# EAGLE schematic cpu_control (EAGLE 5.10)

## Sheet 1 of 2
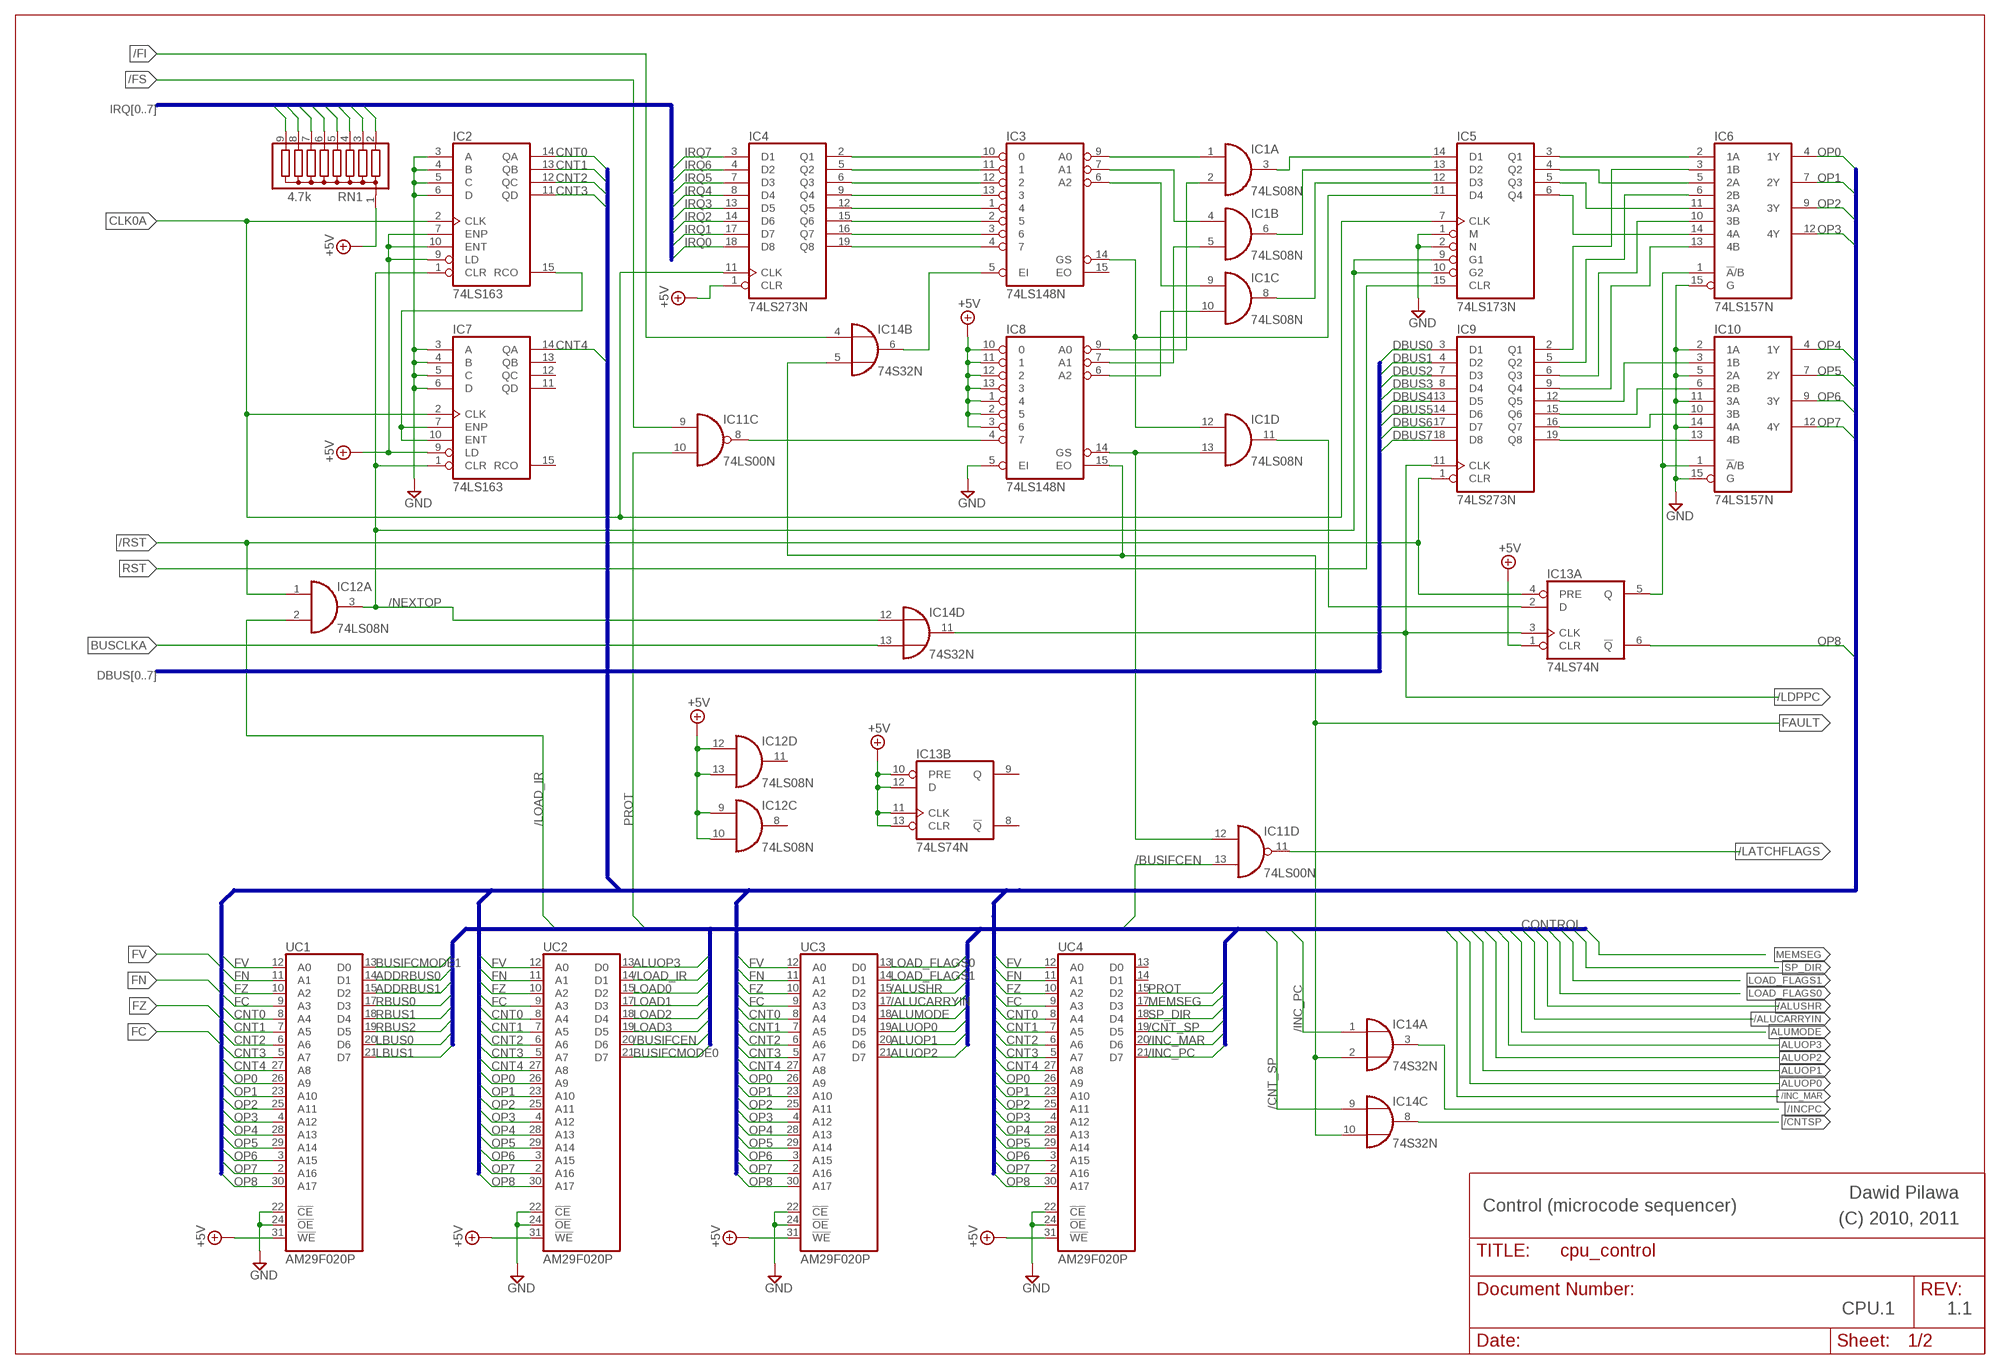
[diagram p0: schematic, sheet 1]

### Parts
IC1  74LS08N  [DIL14]
IC2  74LS163  74160N  [DIL16]
IC3  74LS148N  [DIL16]
IC4  74LS273N  74273N  [DIL20]
IC5  74LS173N  [DIL16]
IC6  74LS157N  [DIL16]
IC7  74LS163  74160N  [DIL16]
IC8  74LS148N  [DIL16]
IC9  74LS273N  74273N  [DIL20]
IC10  74LS157N  [DIL16]
IC11  74LS00N  [DIL14]
IC12  74LS08N  [DIL14]
IC13  74LS74N  [DIL14]
IC14  74S32N  [DIL14]
RN1  4.7k  G08R  [SIL9]
UC1  AM29F020P  [DIL32-6]
UC2  AM29F020P  [DIL32-6]
UC3  AM29F020P  [DIL32-6]
UC4  AM29F020P  [DIL32-6]

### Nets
+5V: IC2.7(ENP) IC2.9(LD) IC2.10(ENT) IC4.1(CLR) IC7.9(LD) IC8.1 IC8.2 IC8.3 IC8.10 IC8.11 IC8.12 IC8.13 IC12.9(C:I0) IC12.10(C:I1) IC12.12(D:I0) IC12.13(D:I1) IC13.1(A:CLR) IC13.10(B:PRE) IC13.11(B:CLK) IC13.12(B:D) IC13.13(B:CLR) RN1.1 UC1.31(!WE) UC2.31(!WE) UC3.31(!WE) UC4.31(!WE) ; also sheet 2
/ALUCARRYIN: UC3.17(D3)
/ALUSHR: UC3.15(D2)
/BUSIFCEN: IC11.13(D:I1) UC2.20(D6) ; also sheet 2
/CNT_SP: IC14.9(C:I0) UC4.19(D5)
/CNTSP: IC14.8(C:O)
/FAULT_PF: IC8.4 IC11.8(C:O)
/FI: IC14.4(B:I0) ; also sheet 2
/FS: IC11.9(C:I0) ; also sheet 2
/INC_MAR: UC4.20(D6)
/INC_PC: IC14.1(A:I0) UC4.21(D7)
/INCPC: IC14.3(A:O)
/LATCHFLAGS: IC11.11(D:O) ; also sheet 2
/LDPPC: IC9.11(CLK) IC13.3(A:CLK) IC14.11(D:O)
/LOAD_IR: IC12.2(A:I1) UC2.14(D1)
/NEXTOP: IC2.1(CLR) IC5.9(G1) IC5.10(G2) IC7.1(CLR) IC12.3(A:O) IC14.12(D:I0)
/RST: IC9.1(CLR) IC12.1(A:I0) IC13.4(A:PRE) ; also sheet 2
ADDRBUS0: UC1.14(D1) ; also sheet 2
ADDRBUS1: UC1.15(D2) ; also sheet 2
ALUMODE: UC3.18(D4)
ALUOP0: UC3.19(D5)
ALUOP1: UC3.20(D6)
ALUOP2: UC3.21(D7)
ALUOP3: UC2.13(D0)
BUSCLKA: IC14.13(D:I1) ; also sheet 2
BUSIFCMODE0: UC2.21(D7) ; also sheet 2
BUSIFCMODE1: UC1.13(D0) ; also sheet 2
CLK0A: IC2.2(CLK) IC4.11(CLK) IC5.7(CLK) IC7.2(CLK)
CNT0: IC2.14(QA) UC1.8(A4) UC2.8(A4) UC3.8(A4) UC4.8(A4)
CNT1: IC2.13(QB) UC1.7(A5) UC2.7(A5) UC3.7(A5) UC4.7(A5)
CNT2: IC2.12(QC) UC1.6(A6) UC2.6(A6) UC3.6(A6) UC4.6(A6)
CNT3: IC2.11(QD) UC1.5(A7) UC2.5(A7) UC3.5(A7) UC4.5(A7)
CNT4: IC7.14(QA) UC1.27(A8) UC2.27(A8) UC3.27(A8) UC4.27(A8)
DBUS0: IC9.3(D1)
DBUS1: IC9.4(D2)
DBUS2: IC9.7(D3)
DBUS3: IC9.8(D4)
DBUS4: IC9.13(D5)
DBUS5: IC9.14(D6)
DBUS6: IC9.17(D7)
DBUS7: IC9.18(D8)
FAULT: IC8.15(EO) IC14.2(A:I1) IC14.5(B:I1) IC14.10(C:I1) ; also sheet 2
FC: UC1.9(A3) UC2.9(A3) UC3.9(A3) UC4.9(A3) ; also sheet 2
FN: UC1.11(A1) UC2.11(A1) UC3.11(A1) UC4.11(A1) ; also sheet 2
FV: UC1.12(A0) UC2.12(A0) UC3.12(A0) UC4.12(A0) ; also sheet 2
FZ: UC1.10(A2) UC2.10(A2) UC3.10(A2) UC4.10(A2) ; also sheet 2
GND: IC2.3(A) IC2.4(B) IC2.5(C) IC2.6(D) IC5.1(M) IC5.2(N) IC6.15(G) IC7.3(A) IC7.4(B) IC7.5(C) IC7.6(D) IC8.5(EI) IC10.2(1A) IC10.5(2A) IC10.11(3A) IC10.14(4A) IC10.15(G) UC1.22(!CE) UC1.24(!OE) UC2.22(!CE) UC2.24(!OE) UC3.22(!CE) UC3.24(!OE) UC4.22(!CE) UC4.24(!OE) ; also sheet 2
IRQ0: IC4.18(D8) RN1.9
IRQ1: IC4.17(D7) RN1.7 RN1.8
IRQ2: IC4.14(D6)
IRQ3: IC4.13(D5) RN1.6
IRQ4: IC4.8(D4) RN1.5
IRQ5: IC4.7(D3) RN1.3 RN1.4
IRQ6: IC4.4(D2)
IRQ7: IC4.3(D1) RN1.2
LBUS0: UC1.20(D6) ; also sheet 2
LBUS1: UC1.21(D7) ; also sheet 2
LOAD0: UC2.15(D2) ; also sheet 2
LOAD1: UC2.17(D3) ; also sheet 2
LOAD2: UC2.18(D4) ; also sheet 2
LOAD3: UC2.19(D5) ; also sheet 2
LOAD_FLAGS0: UC3.13(D0) ; also sheet 2
LOAD_FLAGS1: UC3.14(D1) ; also sheet 2
MEMSEG: UC4.17(D3)
N$1: IC1.1(A:I0) IC3.9(A0)
N$2: IC2.15(RCO) IC7.7(ENP) IC7.10(ENT)
N$3: IC1.2(A:I1) IC8.9(A0)
N$4: IC1.4(B:I0) IC3.7(A1)
N$5: IC1.5(B:I1) IC8.7(A1)
N$6: IC1.10(C:I1) IC8.6(A2)
N$7: IC1.9(C:I0) IC3.6(A2)
N$9: IC1.12(D:I0) IC3.14(GS) IC5.11(D4)
N$10: IC1.13(D:I1) IC8.14(GS) IC11.12(D:I0)
N$11: IC1.3(A:O) IC5.14(D1)
N$12: IC1.6(B:O) IC5.13(D2)
N$13: IC1.8(C:O) IC5.12(D3)
N$14: IC1.11(D:O) IC13.2(A:D)
N$16: IC6.6(2B) IC9.5(Q2)
N$18: IC5.3(Q1) IC6.2(1A)
N$19: IC5.4(Q2) IC6.5(2A)
N$20: IC5.5(Q3) IC6.11(3A)
N$21: IC5.6(Q4) IC6.14(4A)
N$22: IC9.19(Q8) IC10.13(4B)
N$23: IC9.16(Q7) IC10.10(3B)
N$24: IC9.15(Q6) IC10.6(2B)
N$25: IC9.12(Q5) IC10.3(1B)
N$26: IC6.3(1B) IC9.2(Q1)
N$27: IC3.5(EI) IC14.6(B:O)
N$28: IC6.10(3B) IC9.6(Q3)
N$30: IC6.13(4B) IC9.9(Q4)
N$47: IC6.1(!A!/B) IC10.1(!A!/B) IC13.5(A:Q)
N$57: IC3.4 IC4.19(Q8)
N$58: IC3.3 IC4.16(Q7)
N$59: IC3.2 IC4.15(Q6)
N$60: IC3.1 IC4.12(Q5)
N$61: IC3.13 IC4.9(Q4)
N$62: IC3.12 IC4.6(Q3)
N$63: IC3.11 IC4.5(Q2)
N$64: IC3.10 IC4.2(Q1)
OP0: IC6.4(1Y) UC1.26(A9) UC2.26(A9) UC3.26(A9) UC4.26(A9)
OP1: IC6.7(2Y) UC1.23(A10) UC2.23(A10) UC3.23(A10) UC4.23(A10)
OP2: IC6.9(3Y) UC1.25(A11) UC2.25(A11) UC3.25(A11) UC4.25(A11)
OP3: IC6.12(4Y) UC1.4(A12) UC2.4(A12) UC3.4(A12) UC4.4(A12)
OP4: IC10.4(1Y) UC1.28(A13) UC2.28(A13) UC3.28(A13) UC4.28(A13)
OP5: IC10.7(2Y) UC1.29(A14) UC2.29(A14) UC3.29(A14) UC4.29(A14)
OP6: IC10.9(3Y) UC1.3(A15) UC2.3(A15) UC3.3(A15) UC4.3(A15)
OP7: IC10.12(4Y) UC1.2(A16) UC2.2(A16) UC3.2(A16) UC4.2(A16)
OP8: IC13.6(A:!Q) UC1.30(A17) UC2.30(A17) UC3.30(A17) UC4.30(A17)
PROT: IC11.10(C:I1) UC4.15(D2)
RBUS0: UC1.17(D3) ; also sheet 2
RBUS1: UC1.18(D4) ; also sheet 2
RBUS2: UC1.19(D5) ; also sheet 2
RST: IC5.15(CLR) ; also sheet 2
SP_DIR: UC4.18(D4)
Unconnected: IC3.15(EO) IC7.11(QD) IC7.12(QC) IC7.13(QB) IC7.15(RCO) IC12.8(C:O) IC12.11(D:O) IC13.8(B:!Q) IC13.9(B:Q) UC4.13(D0) UC4.14(D1)

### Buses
DBUS[0..7]
UCADR:OP[0..8],CNT[0..4],FC,FZ,FN,FV
IRQ[0..7]
UCODE:LBUS[0..1],RBUS[0..2],ADDRBUS[0..1],BUSIFCMODE[0..1],/BUSIFCEN,LOAD[0..3],/LOAD_IR,ALUOP[0..3],ALUMODE,/ALUCARRYIN,/ALUSHR,LOAD_FLAGS[0..1],/INC_PC,/INC_MAR,/CNT_SP,SP_DIR,MEMSEG,PROT,NC[0..1],NEXTOP

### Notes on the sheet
- CONTROL
- Dawid Pilawa
- Control (microcode sequencer) | (C) 2010, 2011
- CPU.1 | 1.1

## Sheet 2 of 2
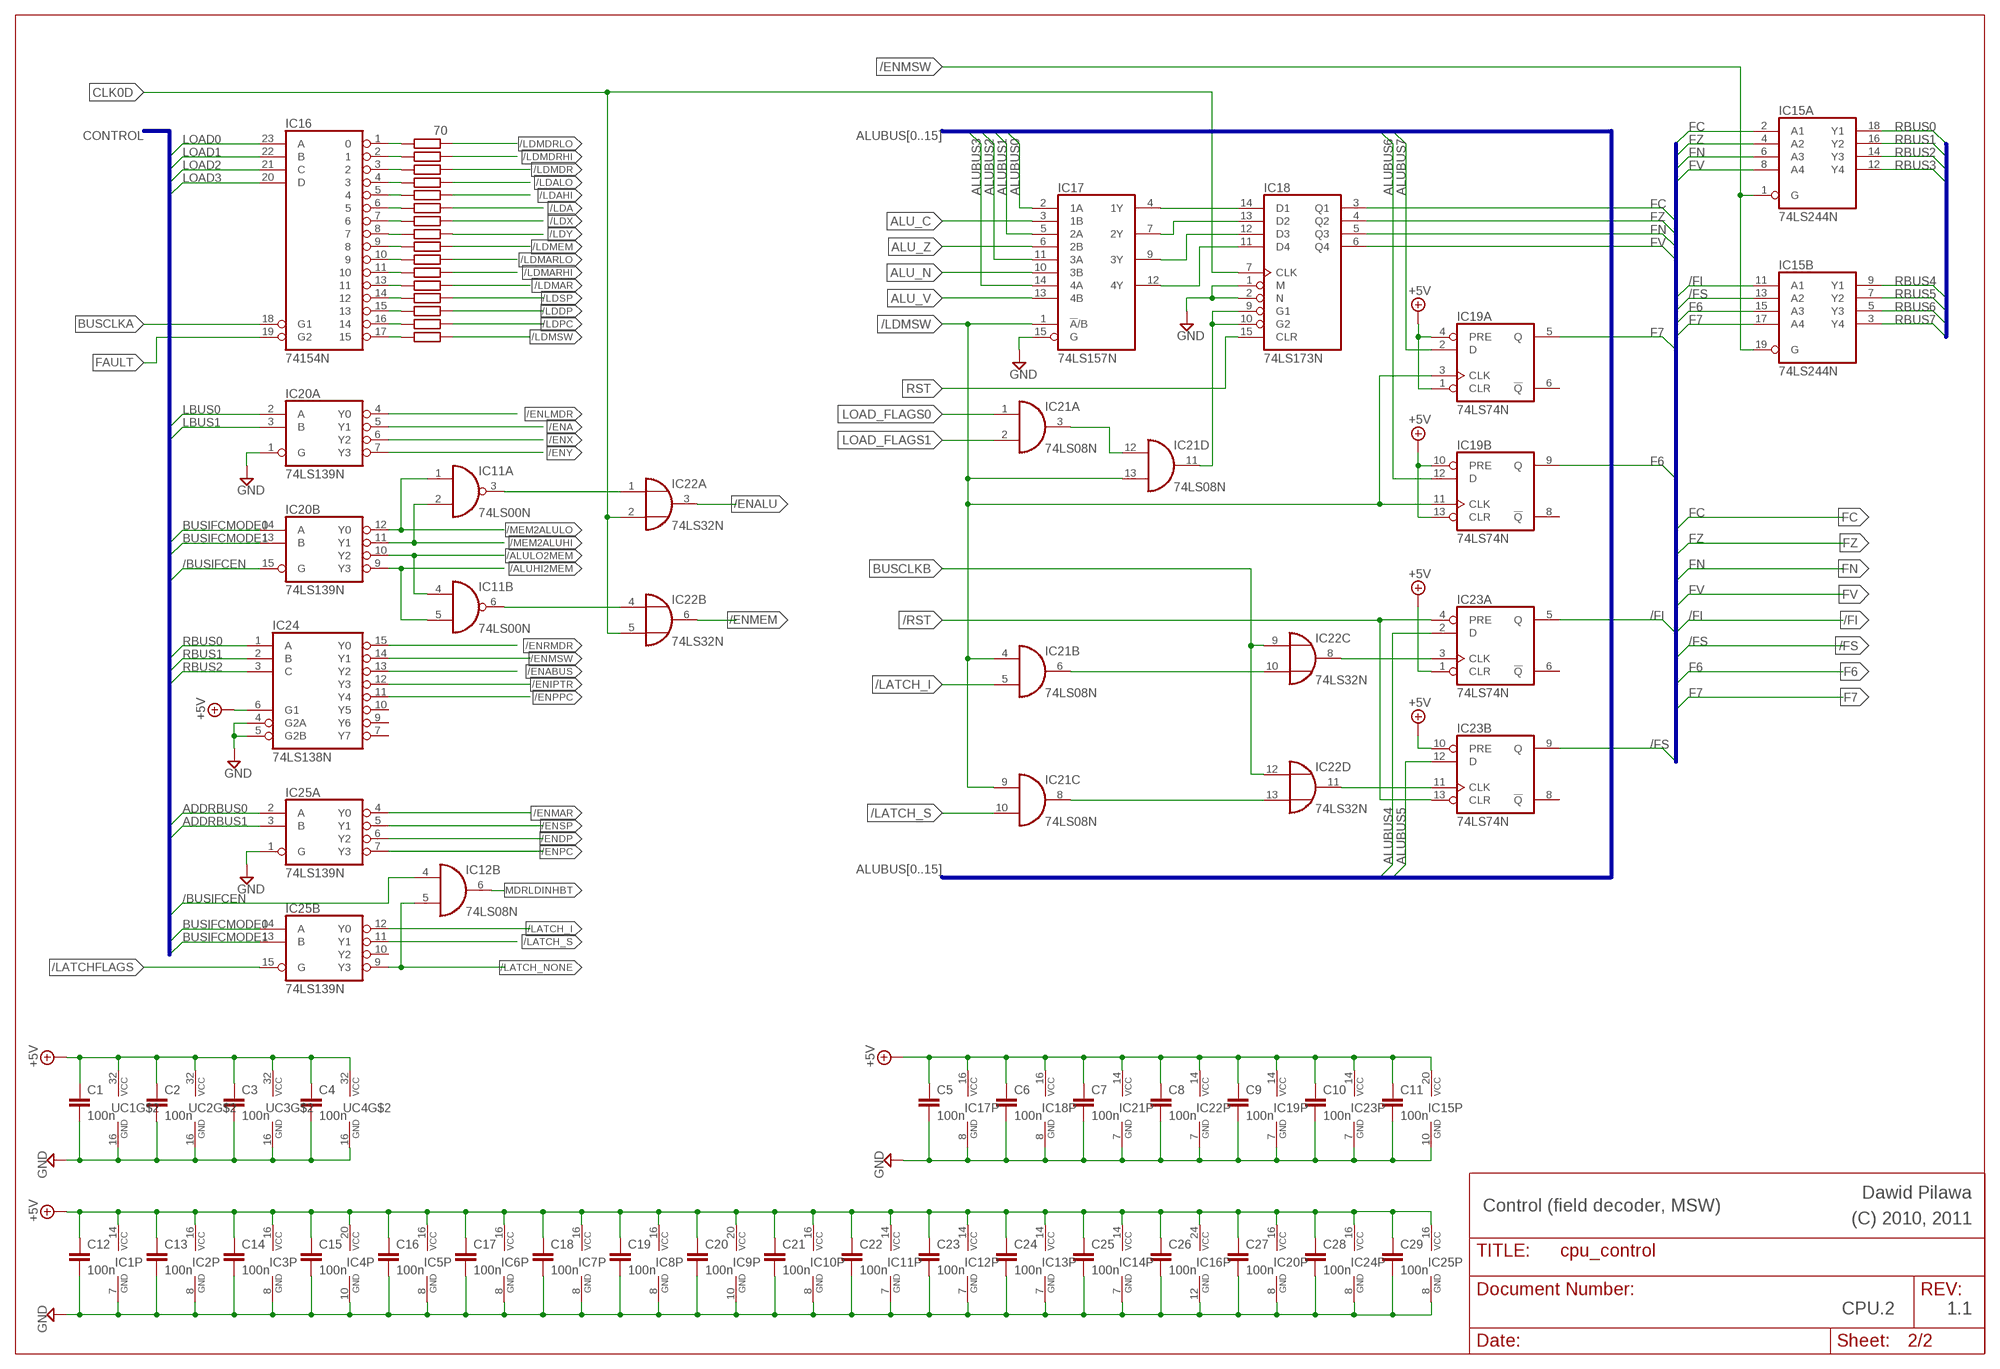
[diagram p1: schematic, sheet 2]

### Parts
C1  100n  C-EU050-024X044  [C050-024X044]
C2  100n  C-EU050-024X044  [C050-024X044]
C3  100n  C-EU050-024X044  [C050-024X044]
C4  100n  C-EU050-024X044  [C050-024X044]
C5  100n  C-EU050-024X044  [C050-024X044]
C6  100n  C-EU050-024X044  [C050-024X044]
C7  100n  C-EU050-024X044  [C050-024X044]
C8  100n  C-EU050-024X044  [C050-024X044]
C9  100n  C-EU050-024X044  [C050-024X044]
C10  100n  C-EU050-024X044  [C050-024X044]
C11  100n  C-EU050-024X044  [C050-024X044]
C12  100n  C-EU050-024X044  [C050-024X044]
C13  100n  C-EU050-024X044  [C050-024X044]
C14  100n  C-EU050-024X044  [C050-024X044]
C15  100n  C-EU050-024X044  [C050-024X044]
C16  100n  C-EU050-024X044  [C050-024X044]
C17  100n  C-EU050-024X044  [C050-024X044]
C18  100n  C-EU050-024X044  [C050-024X044]
C19  100n  C-EU050-024X044  [C050-024X044]
C20  100n  C-EU050-024X044  [C050-024X044]
C21  100n  C-EU050-024X044  [C050-024X044]
C22  100n  C-EU050-024X044  [C050-024X044]
C23  100n  C-EU050-024X044  [C050-024X044]
C24  100n  C-EU050-024X044  [C050-024X044]
C25  100n  C-EU050-024X044  [C050-024X044]
C26  100n  C-EU050-024X044  [C050-024X044]
C27  100n  C-EU050-024X044  [C050-024X044]
C28  100n  C-EU050-024X044  [C050-024X044]
C29  100n  C-EU050-024X044  [C050-024X044]
IC15  74LS244N  [DIL20]
IC16  74154N  [DIL24-6]
IC17  74LS157N  [DIL16]
IC18  74LS173N  [DIL16]
IC19  74LS74N  [DIL14]
IC20  74LS139N  [DIL16]
IC21  74LS08N  [DIL14]
IC22  74LS32N  [DIL14]
IC23  74LS74N  [DIL14]
IC24  74LS138N  [DIL16]
IC25  74LS139N  [DIL16]
R1  70  R-EU_0204/5  [0204/5]
R2  R-EU_0204/5  [0204/5]
R3  R-EU_0204/5  [0204/5]
R4  R-EU_0204/5  [0204/5]
R5  R-EU_0204/5  [0204/5]
R6  R-EU_0204/5  [0204/5]
R7  R-EU_0204/5  [0204/5]
R8  R-EU_0204/5  [0204/5]
R9  R-EU_0204/5  [0204/5]
R10  R-EU_0204/5  [0204/5]
R11  R-EU_0204/5  [0204/5]
R12  R-EU_0204/5  [0204/5]
R13  R-EU_0204/5  [0204/5]
R14  R-EU_0204/5  [0204/5]
R15  R-EU_0204/5  [0204/5]
R16  R-EU_0204/5  [0204/5]

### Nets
+5V: C1.1 C2.1 C3.1 C4.1 C5.1 C6.1 C7.1 C8.1 C9.1 C10.1 C11.1 C12.1 C13.1 C14.1 C15.1 C16.1 C17.1 C18.1 C19.1 C20.1 C21.1 C22.1 C23.1 C24.1 C25.1 C26.1 C27.1 C28.1 C29.1 IC1.14(P:VCC) IC2.16(VCC) IC3.16(VCC) IC4.20(VCC) IC5.16(VCC) IC6.16(VCC) IC7.16(VCC) IC8.16(VCC) IC9.20(VCC) IC10.16(VCC) IC11.14(P:VCC) IC12.14(P:VCC) IC13.14(P:VCC) IC14.14(P:VCC) IC15.20(P:VCC) IC16.24(VCC) IC17.16(VCC) IC18.16(VCC) IC19.1(A:CLR) IC19.4(A:PRE) IC19.10(B:PRE) IC19.13(B:CLR) IC19.14(P:VCC) IC20.16(P:VCC) IC21.14(P:VCC) IC22.14(P:VCC) IC23.1(A:CLR) IC23.10(B:PRE) IC23.14(P:VCC) IC24.6(G1) IC24.16(VCC) IC25.16(P:VCC) UC1.32(AVCC) UC2.32(AVCC) UC3.32(AVCC) UC4.32(AVCC) ; also sheet 1
/ALUHI2MEM: IC11.5(B:I1) IC20.9(B:Y3)
/ALULO2MEM: IC11.4(B:I0) IC20.10(B:Y2)
/BUSIFCEN: IC12.4(B:I0) IC20.15(B:G) ; also sheet 1
/ENA: IC20.5(A:Y1)
/ENABUS: IC24.13(Y2)
/ENALU: IC22.3(A:O)
/ENDP: IC25.6(A:Y2)
/ENIPTR: IC24.12(Y3)
/ENLMDR: IC20.4(A:Y0)
/ENMAR: IC25.4(A:Y0)
/ENMEM: IC22.6(B:O)
/ENMSW: IC15.1(A:G) IC15.19(B:G) IC24.14(Y1)
/ENPC: IC25.7(A:Y3)
/ENPPC: IC24.11(Y4)
/ENRMDR: IC24.15(Y0)
/ENSP: IC25.5(A:Y1)
/ENX: IC20.6(A:Y2)
/ENY: IC20.7(A:Y3)
/FI: IC15.11(B:A1) IC23.5(A:Q) ; also sheet 1
/FS: IC15.13(B:A2) IC23.9(B:Q) ; also sheet 1
/LATCH_I: IC21.5(B:I1) IC25.12(B:Y0)
/LATCH_NONE: IC12.5(B:I1) IC25.9(B:Y3)
/LATCH_S: IC21.10(C:I1) IC25.11(B:Y1)
/LATCHFLAGS: IC25.15(B:G) ; also sheet 1
/LDA: R6.2
/LDAHI: R5.2
/LDALO: R4.2
/LDDP: R14.2
/LDMAR: R12.2
/LDMARHI: R11.2
/LDMARLO: R10.2
/LDMDR: R3.2
/LDMDRHI: R2.2
/LDMDRLO: R1.2
/LDMEM: R9.2
/LDMSW: IC17.1(!A!/B) IC19.3(A:CLK) IC19.11(B:CLK) IC21.4(B:I0) IC21.9(C:I0) IC21.13(D:I1) R16.2
/LDPC: R15.2
/LDSP: R13.2
/LDX: R7.2
/LDY: R8.2
/MEM2ALUHI: IC11.2(A:I1) IC20.11(B:Y1)
/MEM2ALULO: IC11.1(A:I0) IC20.12(B:Y0)
/RST: IC23.4(A:PRE) IC23.13(B:CLR) ; also sheet 1
ADDRBUS0: IC25.2(A:A) ; also sheet 1
ADDRBUS1: IC25.3(A:B) ; also sheet 1
ALU_C: IC17.3(1B)
ALU_N: IC17.10(3B)
ALU_V: IC17.13(4B)
ALU_Z: IC17.6(2B)
ALUBUS0: IC17.2(1A)
ALUBUS1: IC17.5(2A)
ALUBUS2: IC17.11(3A)
ALUBUS3: IC17.14(4A)
ALUBUS4: IC23.2(A:D)
ALUBUS5: IC23.12(B:D)
ALUBUS6: IC19.12(B:D)
ALUBUS7: IC19.2(A:D)
BUSCLKA: IC16.18(G1) ; also sheet 1
BUSCLKB: IC22.9(C:I0) IC22.12(D:I0)
BUSIFCMODE0: IC20.14(B:A) IC25.14(B:A) ; also sheet 1
BUSIFCMODE1: IC20.13(B:B) IC25.13(B:B) ; also sheet 1
CLK0D: IC18.7(CLK) IC22.2(A:I1) IC22.5(B:I1)
F6: IC15.15(B:A3) IC19.9(B:Q)
F7: IC15.17(B:A4) IC19.5(A:Q)
FAULT: IC16.19(G2) ; also sheet 1
FC: IC15.2(A:A1) IC18.3(Q1) ; also sheet 1
FN: IC15.6(A:A3) IC18.5(Q3) ; also sheet 1
FV: IC15.8(A:A4) IC18.6(Q4) ; also sheet 1
FZ: IC15.4(A:A2) IC18.4(Q2) ; also sheet 1
GND: C1.2 C2.2 C3.2 C4.2 C5.2 C6.2 C7.2 C8.2 C9.2 C10.2 C11.2 C12.2 C13.2 C14.2 C15.2 C16.2 C17.2 C18.2 C19.2 C20.2 C21.2 C22.2 C23.2 C24.2 C25.2 C26.2 C27.2 C28.2 C29.2 IC1.7(P:GND) IC2.8(GND) IC3.8(GND) IC4.10(GND) IC5.8(GND) IC6.8(GND) IC7.8(GND) IC8.8(GND) IC9.10(GND) IC10.8(GND) IC11.7(P:GND) IC12.7(P:GND) IC13.7(P:GND) IC14.7(P:GND) IC15.10(P:GND) IC16.12(GND) IC17.8(GND) IC17.15(G) IC18.1(M) IC18.2(N) IC18.8(GND) IC19.7(P:GND) IC20.1(A:G) IC20.8(P:GND) IC21.7(P:GND) IC22.7(P:GND) IC23.7(P:GND) IC24.4(G2A) IC24.5(G2B) IC24.8(GND) IC25.1(A:G) IC25.8(P:GND) UC1.16(AGND) UC2.16(AGND) UC3.16(AGND) UC4.16(AGND) ; also sheet 1
LBUS0: IC20.2(A:A) ; also sheet 1
LBUS1: IC20.3(A:B) ; also sheet 1
LOAD0: IC16.23(A) ; also sheet 1
LOAD1: IC16.22(B) ; also sheet 1
LOAD2: IC16.21(C) ; also sheet 1
LOAD3: IC16.20(D) ; also sheet 1
LOAD_FLAGS0: IC21.1(A:I0) ; also sheet 1
LOAD_FLAGS1: IC21.2(A:I1) ; also sheet 1
MDRLDINHBT: IC12.6(B:O)
N$8: IC11.3(A:O) IC22.1(A:I0)
N$15: IC11.6(B:O) IC22.4(B:I0)
N$17: IC18.9(G1) IC18.10(G2) IC21.11(D:O)
N$31: IC16.1 R1.1
N$32: IC17.4(1Y) IC18.14(D1)
N$33: IC16.2 R2.1
N$34: IC16.3 R3.1
N$35: IC16.4 R4.1
N$36: IC16.5 R5.1
N$37: IC16.6 R6.1
N$38: IC16.7 R7.1
N$39: IC16.8 R8.1
N$40: IC16.9 R9.1
N$41: IC16.10 R10.1
N$42: IC16.11 R11.1
N$43: IC16.13 R12.1
N$44: IC16.14 R13.1
N$45: IC16.15 R14.1
N$46: IC16.16 R15.1
N$48: IC17.7(2Y) IC18.13(D2)
N$49: IC17.9(3Y) IC18.12(D3)
N$50: IC17.12(4Y) IC18.11(D4)
N$51: IC21.3(A:O) IC21.12(D:I0)
N$52: IC22.8(C:O) IC23.3(A:CLK)
N$53: IC22.11(D:O) IC23.11(B:CLK)
N$54: IC21.6(B:O) IC22.10(C:I1)
N$55: IC21.8(C:O) IC22.13(D:I1)
N$56: IC16.17 R16.1
RBUS0: IC15.18(A:Y1) IC24.1(A) ; also sheet 1
RBUS1: IC15.16(A:Y2) IC24.2(B) ; also sheet 1
RBUS2: IC15.14(A:Y3) IC24.3(C) ; also sheet 1
RBUS3: IC15.12(A:Y4)
RBUS4: IC15.9(B:Y1)
RBUS5: IC15.7(B:Y2)
RBUS6: IC15.5(B:Y3)
RBUS7: IC15.3(B:Y4)
RST: IC18.15(CLR) ; also sheet 1
Unconnected: IC19.6(A:!Q) IC19.8(B:!Q) IC23.6(A:!Q) IC23.8(B:!Q) IC24.7(Y7) IC24.9(Y6) IC24.10(Y5) IC25.10(B:Y2)

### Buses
ALUBUS[0..15]
FC,FZ,FN,FV,/FI,/FS,F6,F7
RBUS[0..15]
UCODE:LBUS[0..1],RBUS[0..2],ADDRBUS[0..1],BUSIFCMODE[0..1],/BUSIFCEN,LOAD[0..3],/LOAD_IR,ALUOP[0..3],ALUMODE,/ALUCARRYIN,/ALUSHR,LOAD_FLAGS[0..1],/INC_PC,/INC_MAR,/CNT_SP,SP_DIR,MEMSEG,PROT,NC[0..1],NEXTOP

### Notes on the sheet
- CONTROL
- Dawid Pilawa
- Control (field decoder, MSW) | (C) 2010, 2011
- CPU.2 | 1.1

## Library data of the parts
C1-C29 = rcl:C-EU: CAPACITOR, European symbol
IC1 IC12 IC21 = 74xx-eu:74*08: Quad 2-input AND gate
IC2 IC7 = 74xx-eu:74*160: Synchronous 4-bit COUNTER
IC3 IC8 = 74xx-eu:74*148: 10-line to 4-line and 8-line to 3-line PRIORITY ENCODER
IC4 IC9 = 74xx-eu:74*273: Octal D type FLIP FLOP, clear
IC5 IC18 = 74xx-eu:74*173: 4-bit D type REGISTER, 3-state
IC6 IC10 IC17 = 74xx-eu:74*157: Quadruple 2-line to 1-line data SELECTOR/MULTIPLEXER
IC11 = 74xx-eu:74*00: Quad 2-input NAND gate
IC13 IC19 IC23 = 74xx-eu:74*74: Dual D type positive edge triggered FLIP FLOP, preset and clear
IC14 IC22 = 74xx-eu:74*32: Quad 2-input OR gate
IC15 = 74xx-eu:74*244: Octal BUFFER and LINE DRIVER, 3-state
IC16 = 74xx-eu:74*154: 4-line to 16-line data SELECTOR/MULTIPLEXER
IC20 IC25 = 74xx-eu:74*139: Dual 2-line to 4-line DECODER/DEMULTIPLEXER
IC24 = 74xx-eu:74*138: 3-line to 8-line DECODER/DEMULTIPLEXER
R1-R16 = rcl:R-EU_: RESISTOR, European symbol
RN1 = resistor-sil:G08R: SIL RESISTOR
UC1-UC4 = am29-memory:AM29F020P: 20F020 - 256kB FLASH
